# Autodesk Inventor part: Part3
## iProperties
Shininess: 77.0
Angle Display Precision: 2
Document Length Units: 11269
Document Angle Units: 11279
Document Time Units: 11290
Document Mass Units: 11283
Document Length Units Precision: 3
Document Angle Units Precision: 2
Created: 2002-04
Part Number: Part3
Document SubType Name: Sheet Metal
Density: 0.0
Volumn: 0.0
Area: 0.0
PropertySet Name: Model Information
Control State: 0
Master: False
Checked Out: False
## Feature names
1. Plate1
2. Plate6
3. Bend5
4. Plate7
5. Bend7
6. Cut1
